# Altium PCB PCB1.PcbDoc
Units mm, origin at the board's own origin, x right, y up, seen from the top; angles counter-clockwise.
Board outline 100 x 100 mm, 4 copper layers (Top Layer, Layer 1, Layer 2, Bottom Layer), stack 1.578 mm thick; 83 components, 35 nets, 174 pads, 412 vias.
Unrouted connection lines stored in the file: 39.
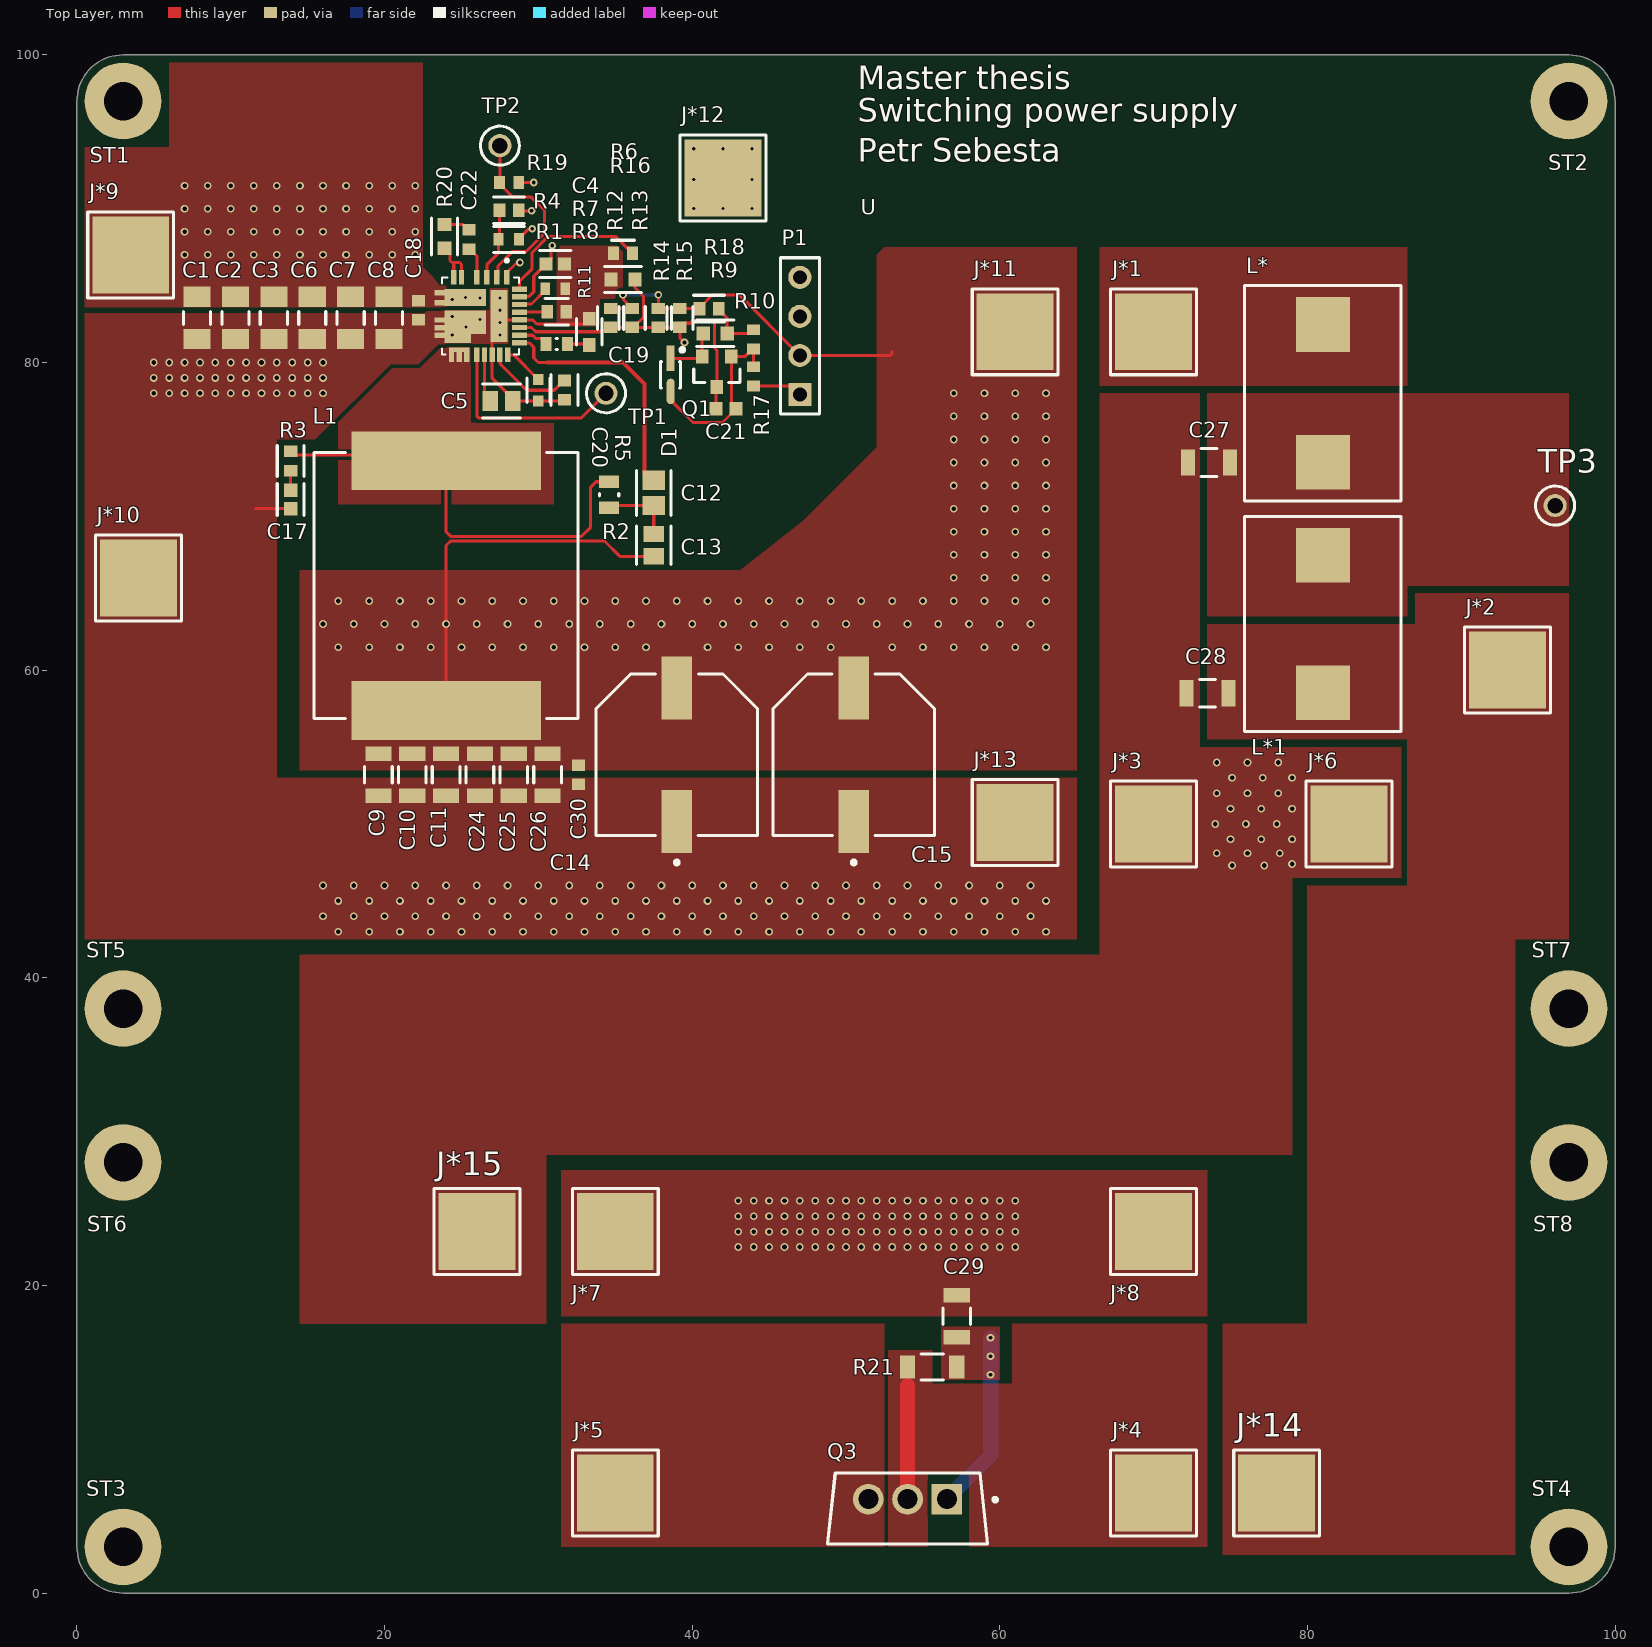
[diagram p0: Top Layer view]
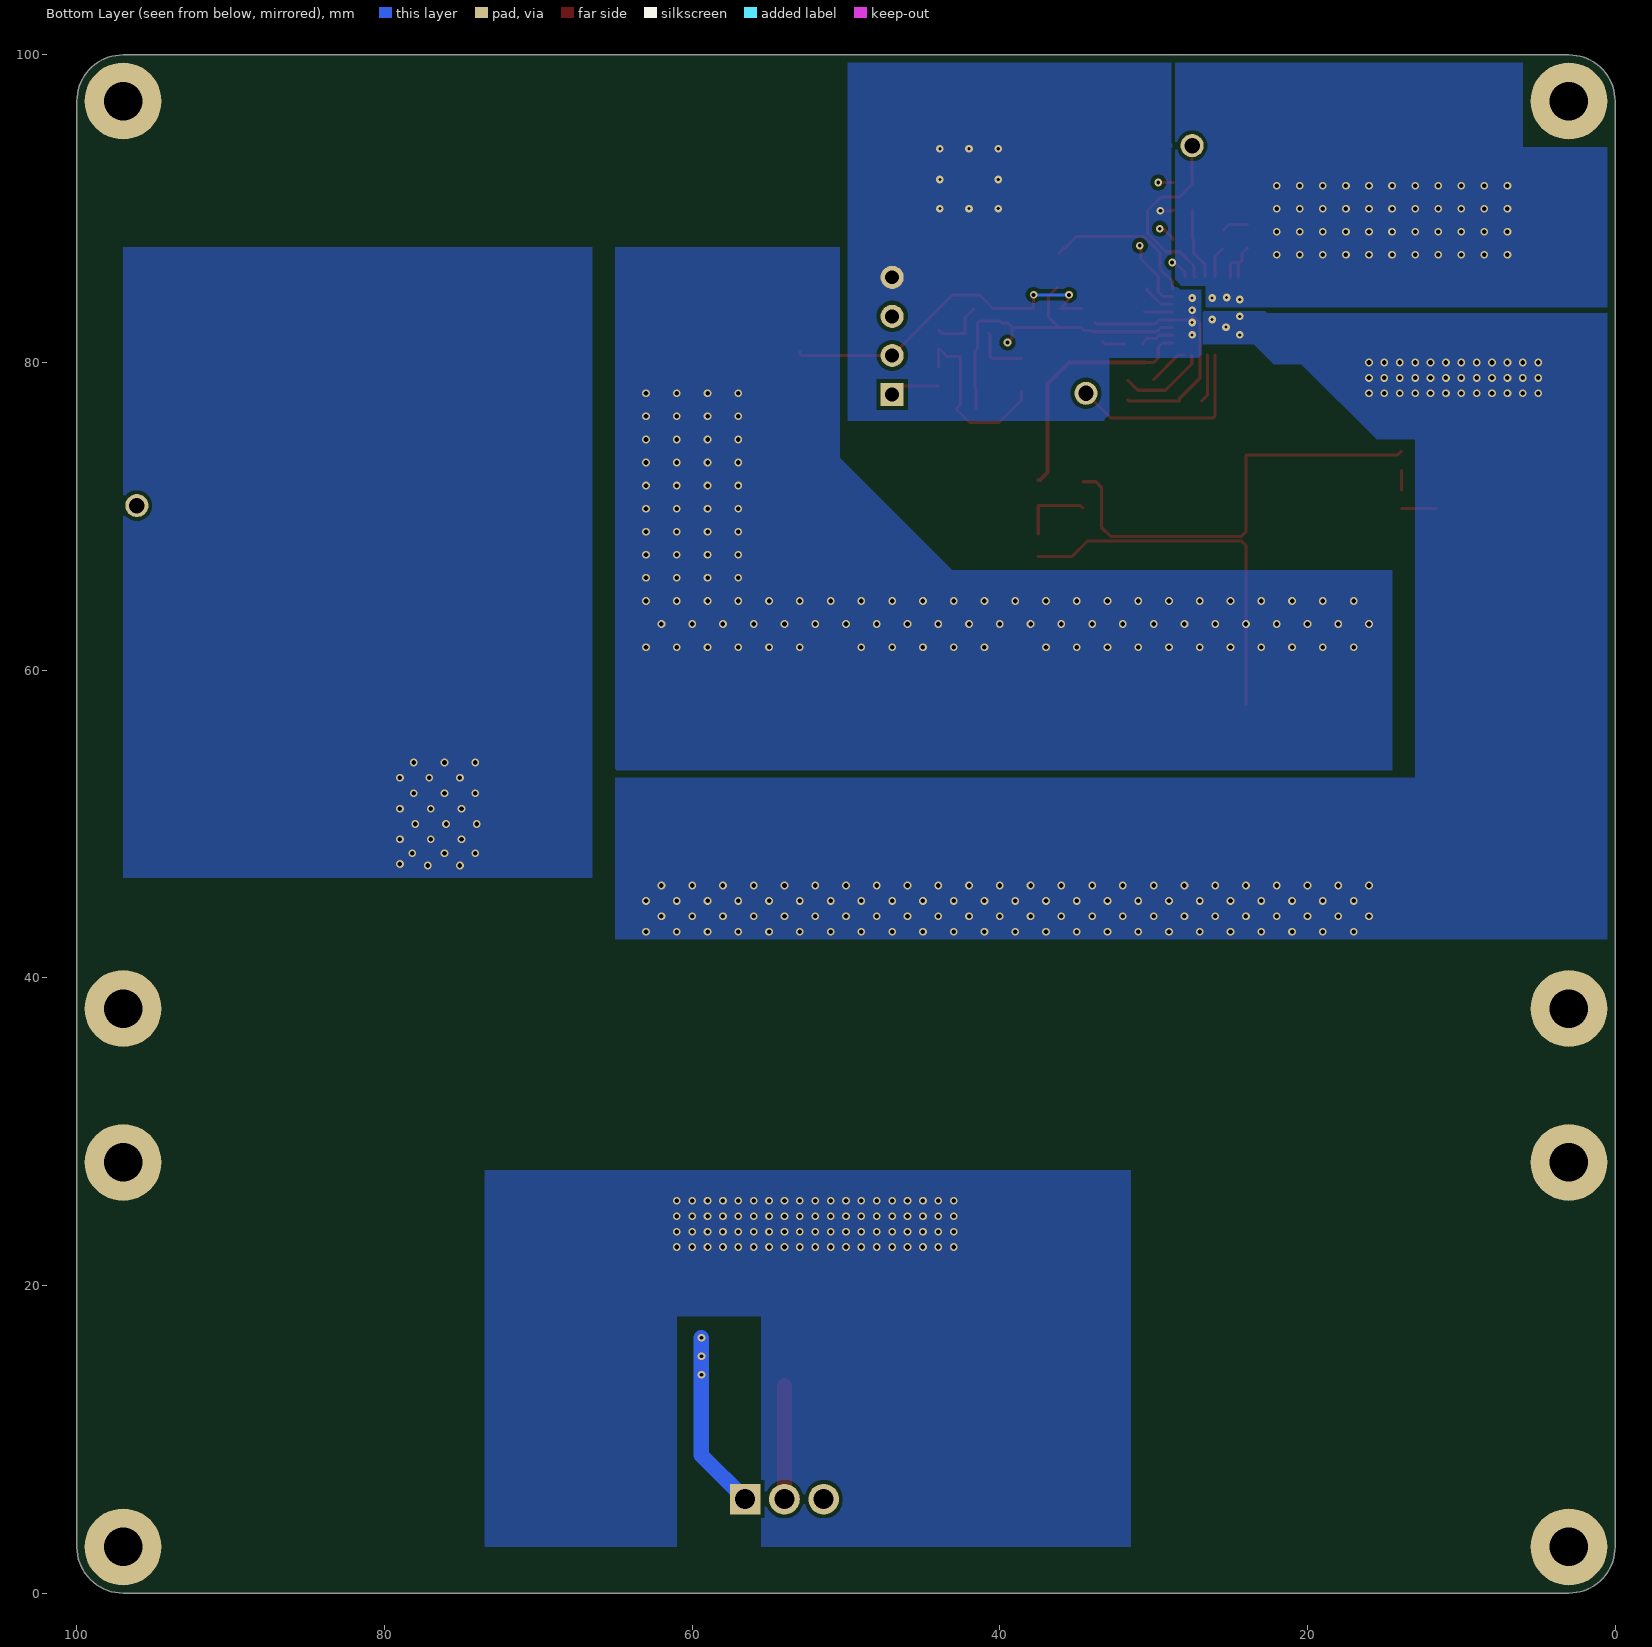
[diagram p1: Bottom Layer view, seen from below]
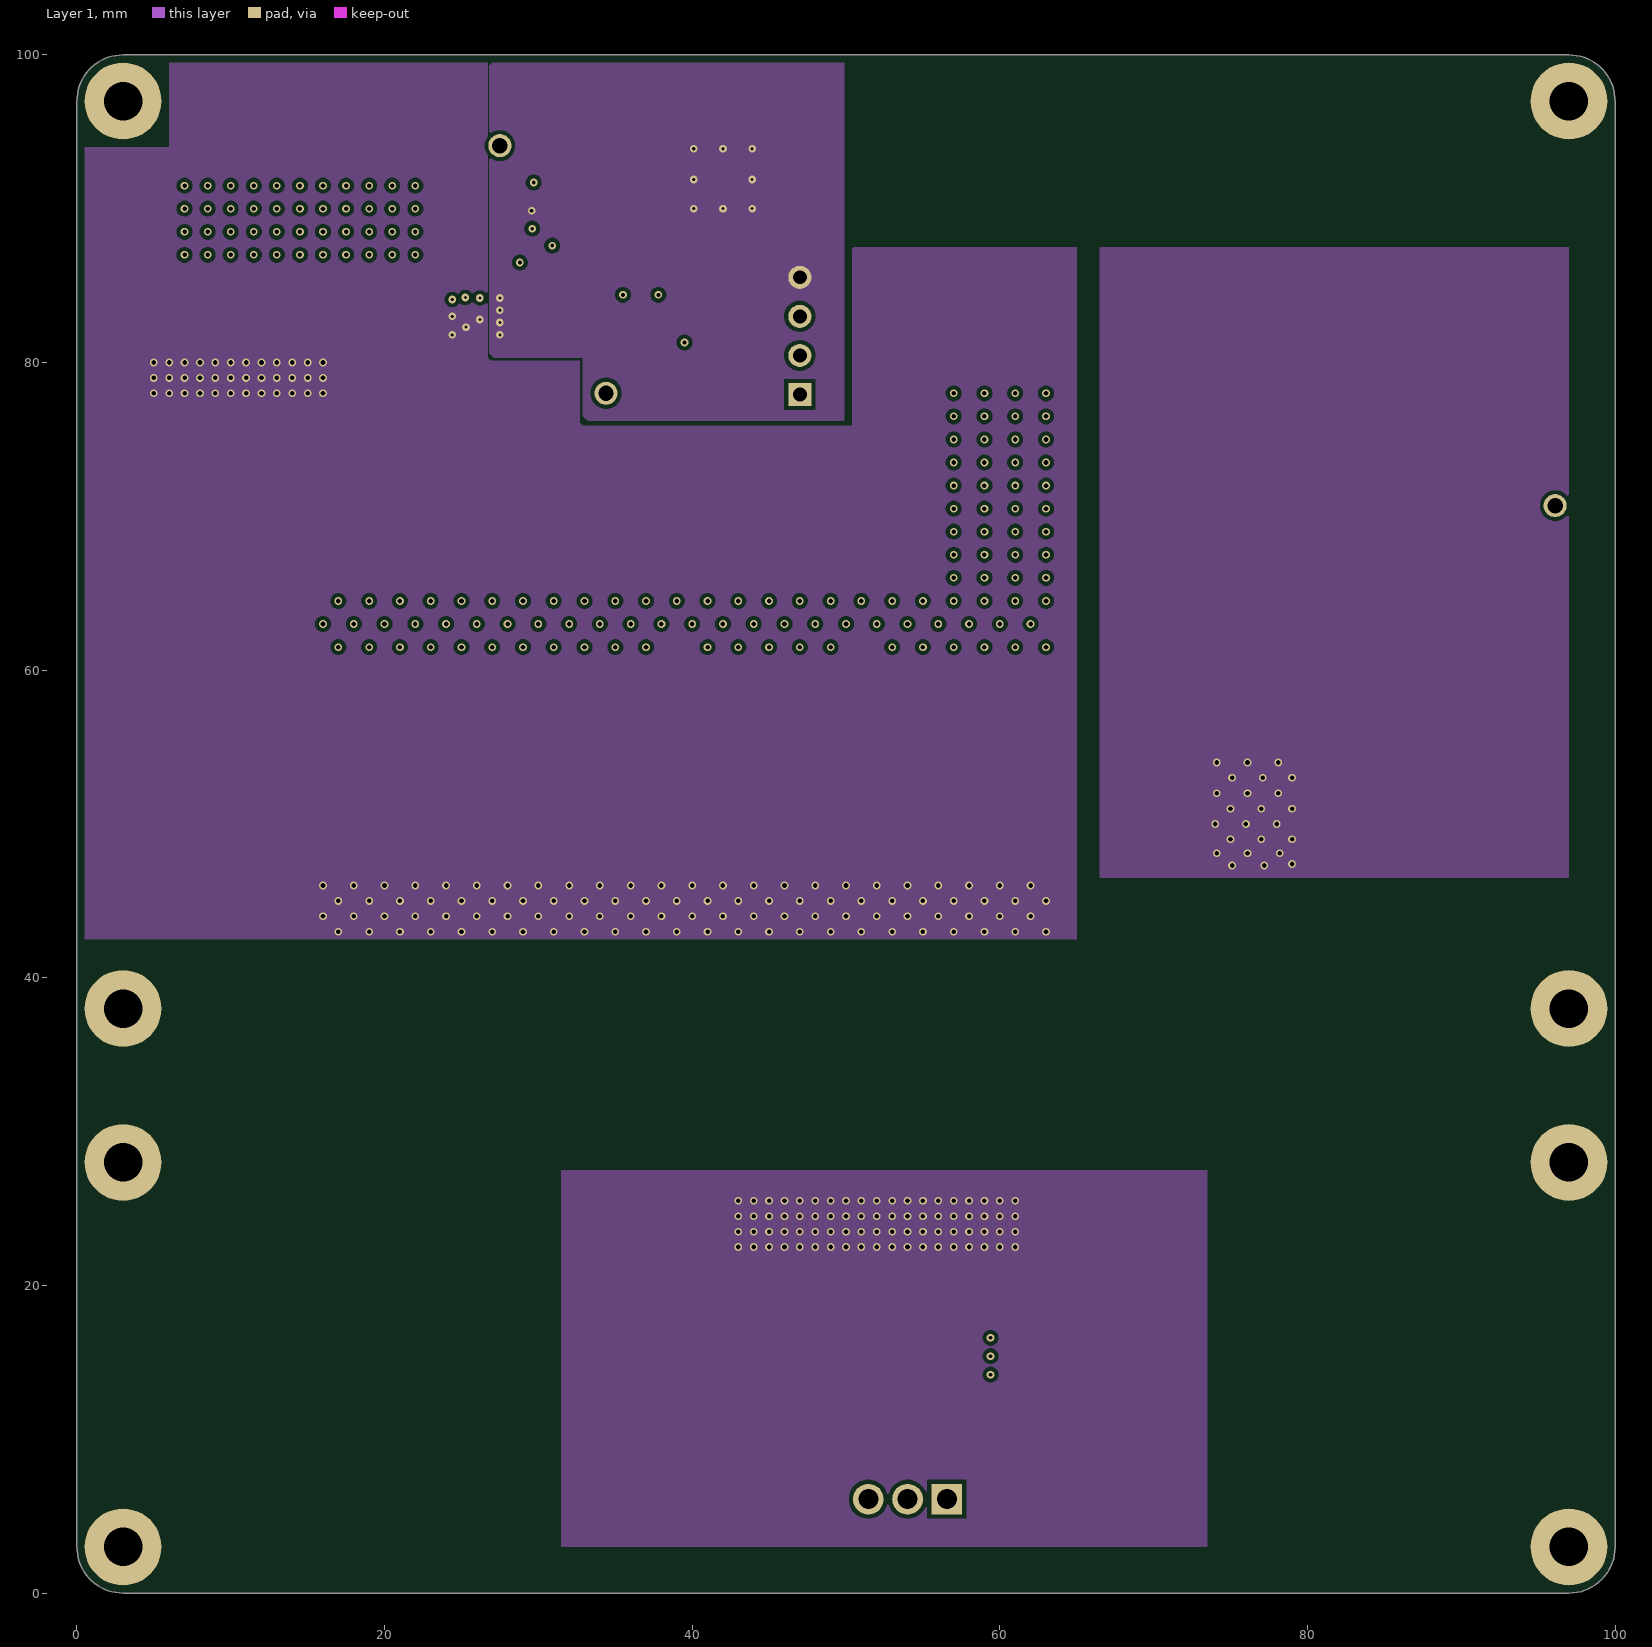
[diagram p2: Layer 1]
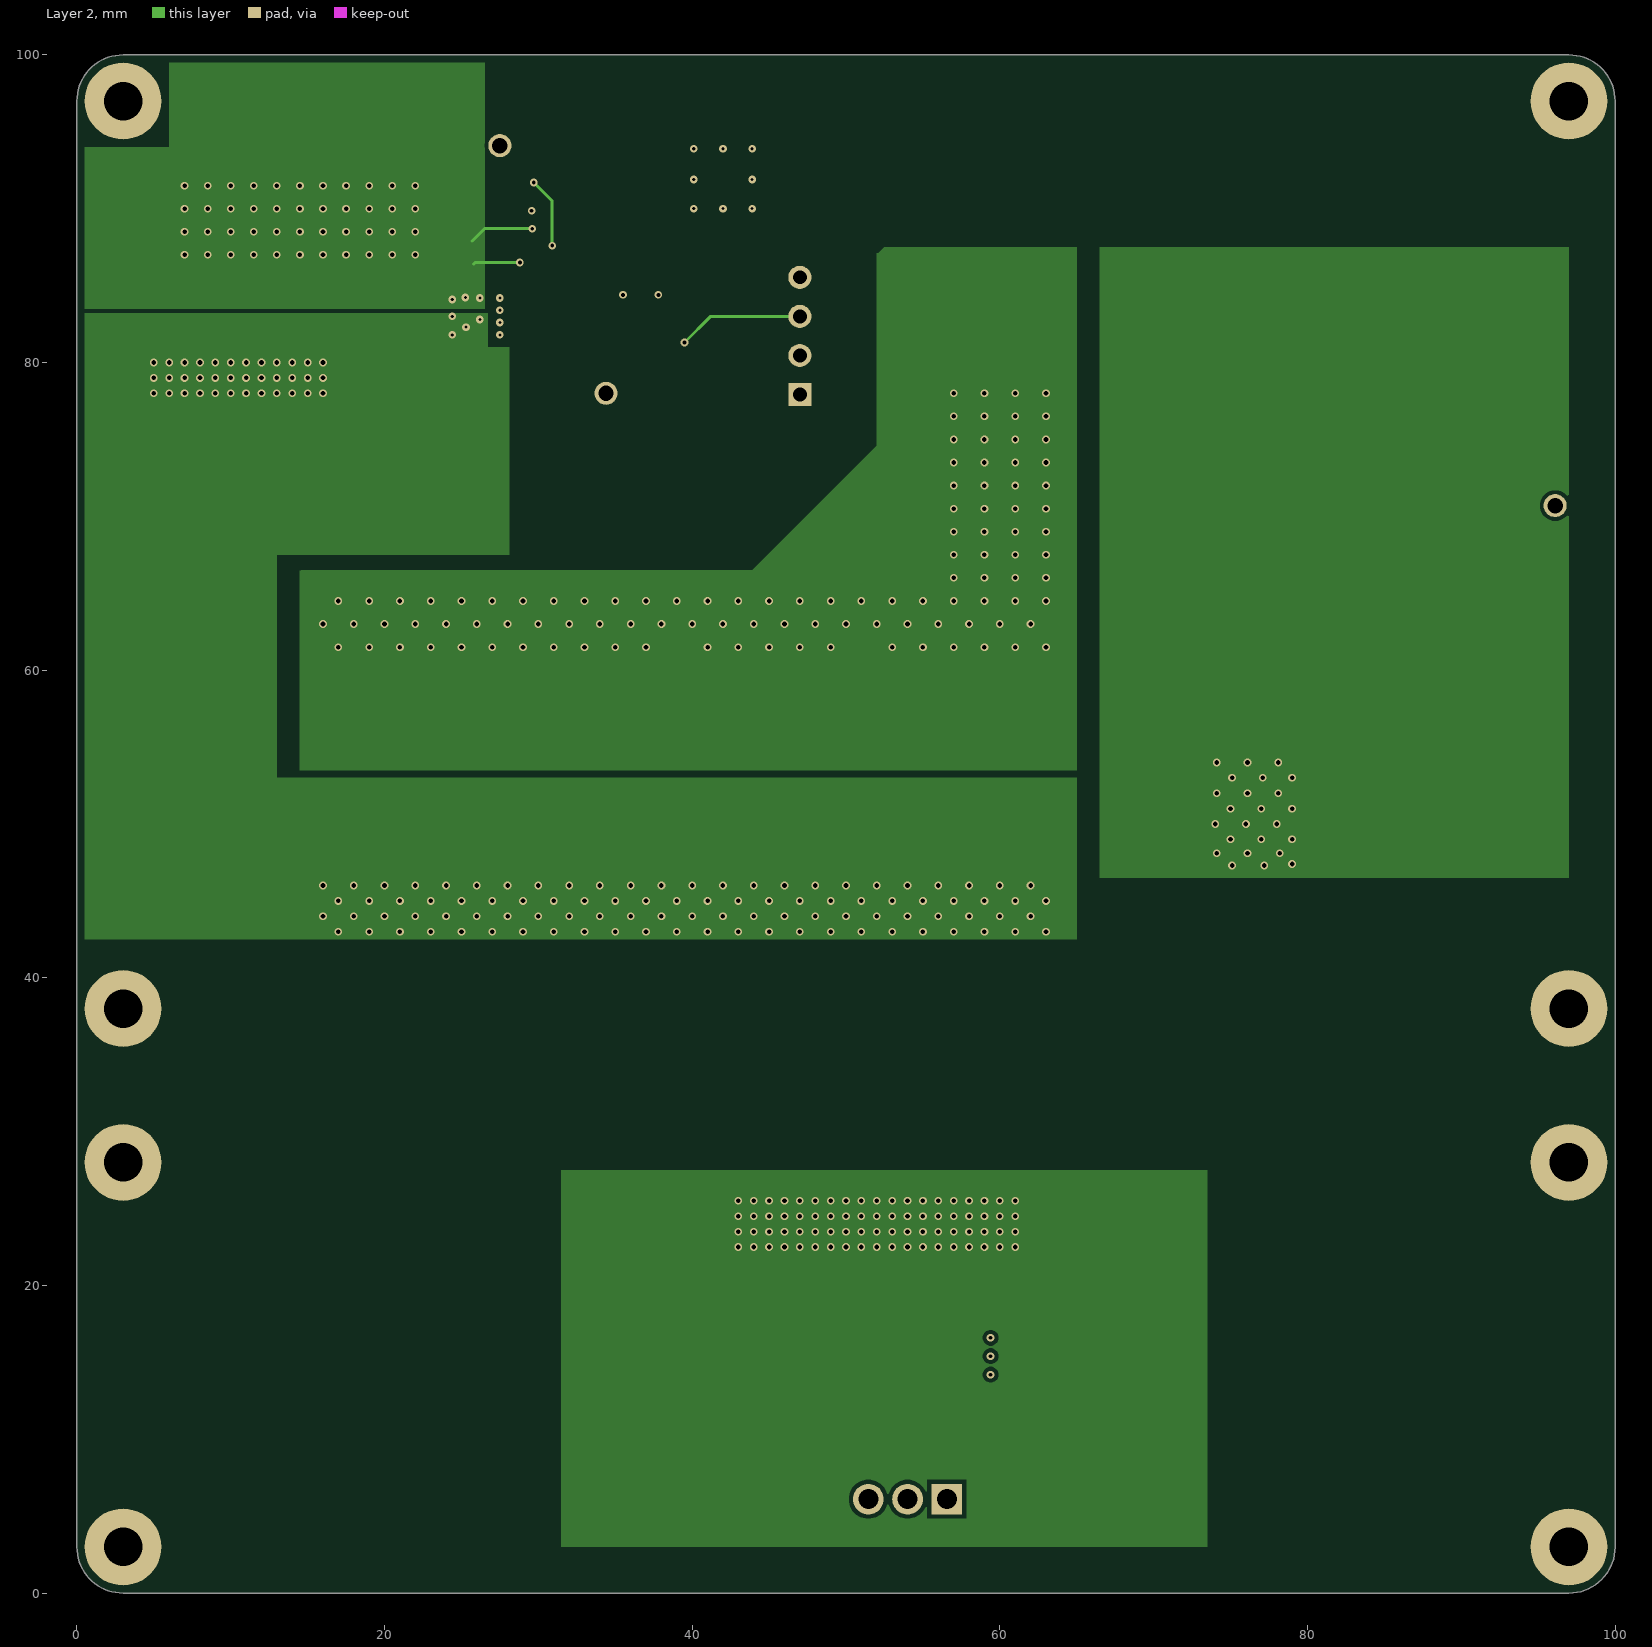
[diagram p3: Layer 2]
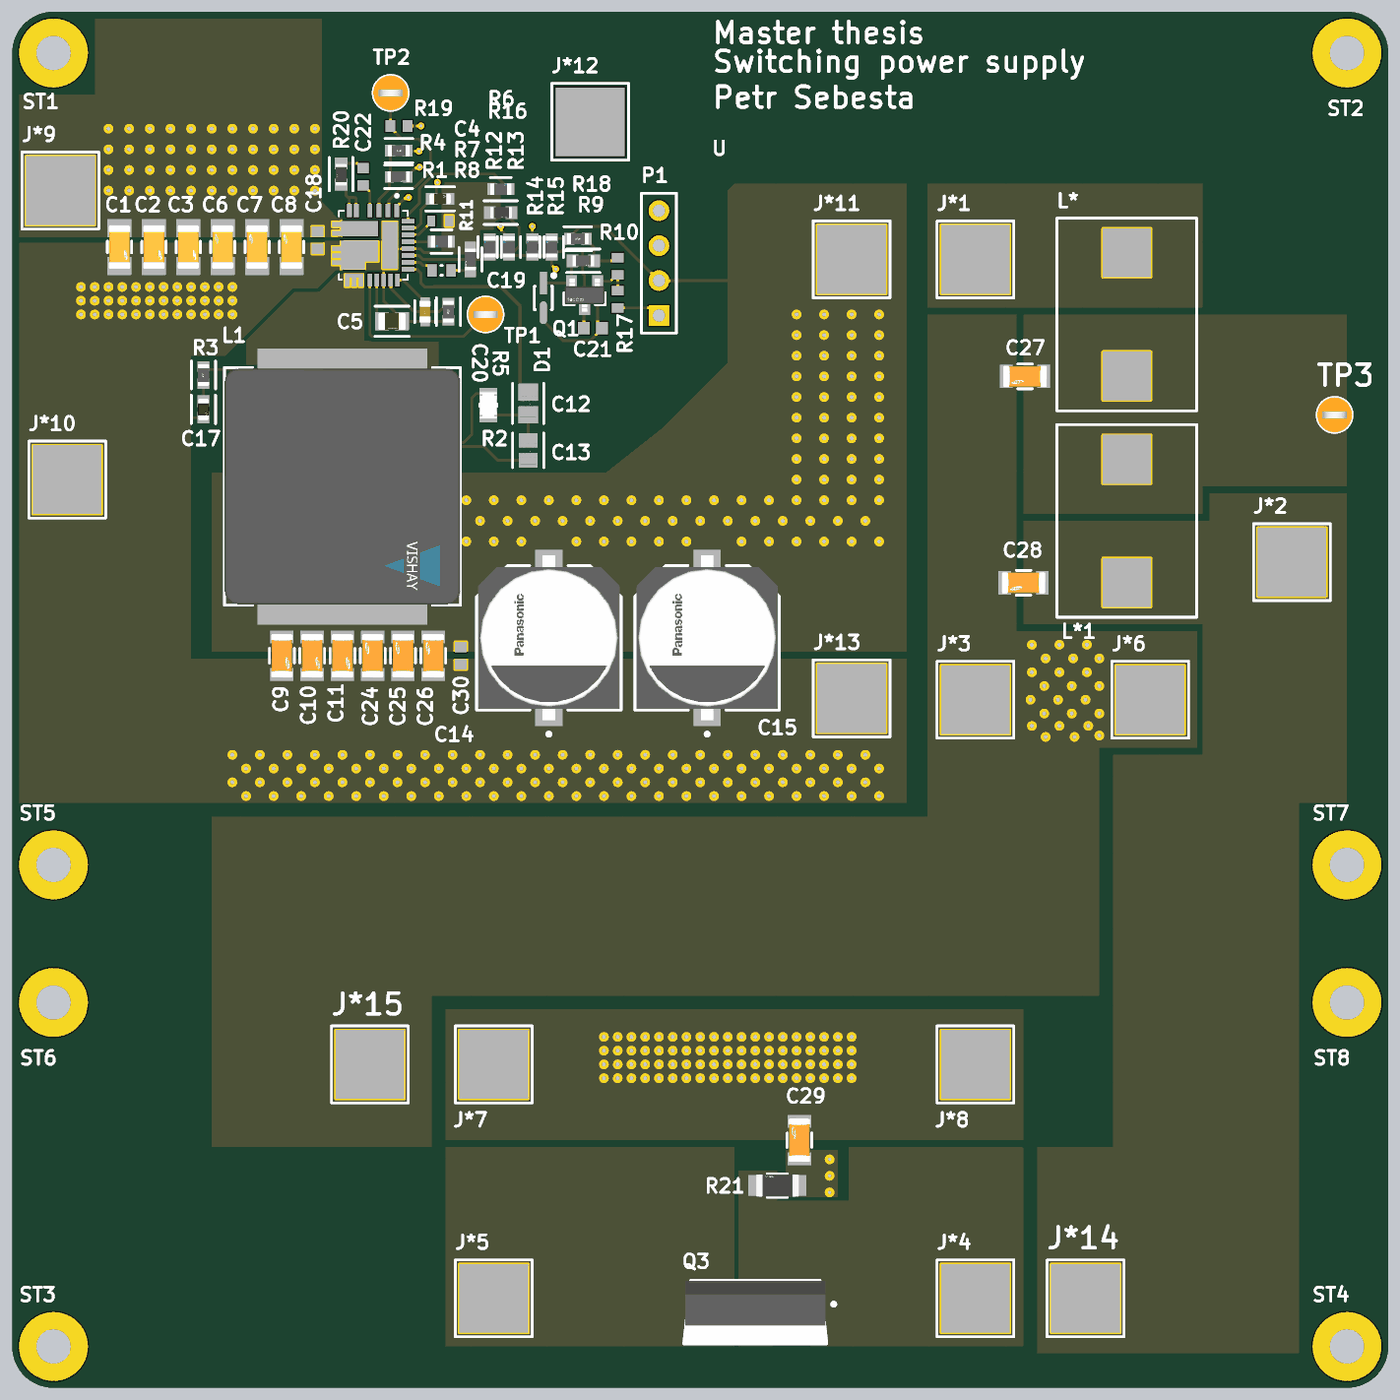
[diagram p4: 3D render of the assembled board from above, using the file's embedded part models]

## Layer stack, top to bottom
Top Solder: solder mask 0.0203, Solder Resist, Dk 3.8
Top Layer: signal copper 0.0356
Dielectric 2: prepreg 0.2104, PP-006, Dk 4.6
Layer 1: signal copper 0.0152
Dielectric 1: dielectric 1.056, FR-4, Dk 4.6
Layer 2: signal copper 0.0152
Dielectric 3: prepreg 0.2104, PP-006, Dk 4.6
Bottom Layer: signal copper 0.0356
Bottom Solder: solder mask 0.0203, Solder Resist, Dk 3.8

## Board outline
0,3 0,97 cw(c3,97) 3,100 97,100 cw(c97,97) 100,97 100,3 cw(c97,3) 97,0 3,0 cw(c3,3)

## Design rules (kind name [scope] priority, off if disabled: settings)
Clearance [All] p1: gap=0.254 ignorepadtopadclearanceinfootprint=FALSE except(0: Arc-Hole Track-Hole SMDPad-Hole THPad-Hole Via-Hole Fill-Hole Poly-Hole Region-Hole Text-Hole; 0.1: Arc-Arc Arc-Track Track-Track; 0.127: SMDPad-SMDPad; 0.2: Arc-SMDPad Track-SMDPad)
MinimumSolderMaskSliver [All] p1: minsoldermaskwidth=0
PolygonConnect PolygonConnect_18 [All vs IsNamedPolygon('NONET_L01_P-001') Or IsNamedPolygon('NONET_L01_P-001') Or IsNamedPolygon('NONET_L01_P-001') Or IsNamedPolygon('NONET_L01_P-001') Or IsNamedPolygon('NONET_L01_P-001') Or IsNamedPolygon('NONET_L01_P-001') Or IsNamedPolygon('NONET_L01_P-001')] p1: connectstyle=Direct reliefconductorwidth=0.254 reliefentries=4 polygonreliefangle="90 Angle" airgapwidth=0.254
PolygonConnect PolygonConnect_17 [All vs IsNamedPolygon('AGND_L02_P016') Or IsNamedPolygon('AGND_L02_P020') Or IsNamedPolygon('AGND_L03_P014') Or IsNamedPolygon('VCC_L03_P008') Or IsNamedPolygon('VOUT_L03_P015') Or IsNamedPolygon('AGND_L04_P022') Or IsNamedPolygon('AGND_L04_P024') Or IsNamedPolygon('VOUT_L04_P023') Or IsNamedPolygon('VCC_L04_P021')] p2: connectstyle=Direct reliefconductorwidth=0.254 reliefentries=4 polygonreliefangle="90 Angle" airgapwidth=0.254
PolygonConnect PolygonConnect_16 [All vs IsNamedPolygon('VOUT_L01_P010')] p3: connectstyle=Direct reliefconductorwidth=0.254 reliefentries=4 polygonreliefangle="90 Angle" airgapwidth=0.254
PolygonConnect PolygonConnect_15 [All vs IsNamedPolygon('VCC_L01_P000')] p4: connectstyle=Direct reliefconductorwidth=0.254 reliefentries=4 polygonreliefangle="90 Angle" airgapwidth=0.254
PolygonConnect PolygonConnect_14 [All vs IsNamedPolygon('AGND_L01_P011')] p5: connectstyle=Direct reliefconductorwidth=0.254 reliefentries=4 polygonreliefangle="90 Angle" airgapwidth=0.254
PolygonConnect PolygonConnect_13 [All vs IsNamedPolygon('AGND_L01_P007')] p6: connectstyle=Direct reliefconductorwidth=0.254 reliefentries=4 polygonreliefangle="90 Angle" airgapwidth=0.254
PolygonConnect PolygonConnect_12 [All vs IsNamedPolygon('AGND_L01_P006')] p7: connectstyle=Direct reliefconductorwidth=0.254 reliefentries=4 polygonreliefangle="90 Angle" airgapwidth=0.254
PolygonConnect PolygonConnect_11 [All vs IsNamedPolygon('AGND_L01_P006')] p8: connectstyle=Direct reliefconductorwidth=0.254 reliefentries=4 polygonreliefangle="90 Angle" airgapwidth=0.254
PolygonConnect PolygonConnect_10 [All vs IsNamedPolygon('AGND_L01_P005')] p9: connectstyle=Direct reliefconductorwidth=0.254 reliefentries=4 polygonreliefangle="90 Angle" airgapwidth=0.254
PolygonConnect PolygonConnect_9 [All vs IsNamedPolygon('AGND_L01_P005')] p10: connectstyle=Direct reliefconductorwidth=0.254 reliefentries=4 polygonreliefangle="90 Angle" airgapwidth=0.254
PolygonConnect PolygonConnect_8 [All vs IsNamedPolygon('AGND_L01_P004')] p11: connectstyle=Direct reliefconductorwidth=0.254 reliefentries=4 polygonreliefangle="90 Angle" airgapwidth=0.254
PolygonConnect PolygonConnect_7 [All vs IsNamedPolygon('AGND_L01_P003')] p12: connectstyle=Direct reliefconductorwidth=0.254 reliefentries=4 polygonreliefangle="90 Angle" airgapwidth=0.254
PolygonConnect DirectConnect [All vs IsNamedPolygon('AGND_L01_P001')] p13: connectstyle=Direct reliefconductorwidth=0.254 reliefentries=4 polygonreliefangle="90 Angle" airgapwidth=0.254
PolygonConnect PolygonConnect_6 [All vs IsNamedPolygon('GND_L01_P003')] p14: connectstyle=Direct reliefconductorwidth=0.254 reliefentries=4 polygonreliefangle="90 Angle" airgapwidth=0.254
PolygonConnect PolygonConnect_5 [All vs IsNamedPolygon('NETL1_1_L01_P002')] p15: connectstyle=Direct reliefconductorwidth=0.254 reliefentries=4 polygonreliefangle="90 Angle" airgapwidth=0.254
PolygonConnect PolygonConnect_4 [All vs IsNamedPolygon('GND_L01_P001')] p16: connectstyle=Direct reliefconductorwidth=0.254 reliefentries=4 polygonreliefangle="90 Angle" airgapwidth=0.254
PolygonConnect PolygonConnect_3 [All vs IsNamedPolygon('VCC_L01_P000')] p17: connectstyle=Direct reliefconductorwidth=0.254 reliefentries=4 polygonreliefangle="90 Angle" airgapwidth=0.254
PolygonConnect PolygonConnect_2 [All vs IsNamedPolygon('VCC_L01_P-001')] p18: connectstyle=Direct reliefconductorwidth=0.254 reliefentries=4 polygonreliefangle="90 Angle" airgapwidth=0.254
PolygonConnect PolygonConnect_1 [All vs IsNamedPolygon('VCC_L01_P000')] p19: connectstyle=Direct reliefconductorwidth=0.254 reliefentries=4 polygonreliefangle="90 Angle" airgapwidth=0.254
PolygonConnect [All] p20: connectstyle=Relief reliefconductorwidth=0.254 reliefentries=4 polygonreliefangle="90 Angle" airgapwidth=0.254
RoutingVias [All] p1: holewidth=0.25 width=0.5 viastyle="Through Hole" minholewidth=0.2 minwidth=0.5 maxholewidth=3.6 maxwidth=10
SilkToSilkClearance [All] p1: silktosilkclearance=0
SilkToSolderMaskClearance [IsPad] p1: minsilkscreentomaskgap=0 clearancetoexposedcopper=TRUE
SolderMaskExpansion [All] p1: expansion=0.102 istentingtop=FALSE
Width [All] p1: maxlimit=1 minlimit=0.2 preferedwidth=0.2
27 further rules are at their usual default settings.

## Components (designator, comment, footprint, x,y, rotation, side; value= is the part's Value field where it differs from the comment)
C1 "CL31B225KBHNNNF" FP-CL31-IPC_B 7.8,82.9 r270 top
C2 "CL31B225KBHNNNF" FP-CL31-IPC_B 10.3,82.9 r270 top
C3 "CL31B225KBHNNNF" FP-CL31-IPC_B 12.8,82.9 r270 top
C4 "UMK107AB7105KA-T" FP-0603-L_1_6_0_15-W_0_8-IPC_C 31.1,86.4 r0 top
C5 "TMK212AB7475KG-T" FP-0805-L_2_0_0_15-W_1_25-IPC_C 27.6,77.5 r0 top
C6 "CL31B225KBHNNNF" FP-CL31-IPC_B 15.3,82.9 r90 top
C7 "CL31B225KBHNNNF" FP-CL31-IPC_B 17.8,82.9 r90 top
C8 "CL31B225KBHNNNF" FP-CL31-IPC_B 20.3,82.9 r90 top
C9 "CL31B106KBHNNNE" FP-CL31B106KBHNNNE-MFG 19.6,53.2 r270 top value=10uF
C10 "CL31B106KBHNNNE" FP-CL31B106KBHNNNE-MFG 21.8,53.2 r270 top value=10uF
C11 "CL31B106KBHNNNE" FP-CL31B106KBHNNNE-MFG 24,53.2 r270 top value=10uF
C12 "CL21B392KBANNNC" FP-CL21-IPC_B 37.5,71.526 r270 top
C13 "CL21B223KBANNWC" FP-CL21-IPC_C 37.5,68.126 r270 top
C14 "EEEFP1V331AP" FP-FPG-MFG 39,54.5 r90 top
C15 "EEEFP1V331AP" FP-FPG-MFG 50.5,54.5 r90 top
C17 "UMK107AB7105KA-T" FP-0603-L_1_6_0_15-W_0_8-IPC_C 13.9,71.1 r270 top
C18 "CL10B104KB8NNNC" SAMS-C0603-2_L 22.2,83.4 r90 top
C19 "CAP 680pF 50V 0603(1608)" CAPC0603(1608)100_L 31.2,81.2 r180 top value=680pF
C20 "C1608X7R1H103M080AA" FP-C1608-080-0_1-MFG 30,78.2 r90 top
C21 "06035C471K4T2A" CAPC1608X90X35LL15T15 42.2,77 r0 top value=470p
C22 "CL10B104KB8NNNC" SAMS-C0603-2_L 25.5,88 r90 top
C24 "CL31B106KBHNNNE" FP-CL31B106KBHNNNE-MFG 26.2,53.2 r90 top value=10uF
C25 "CL31B106KBHNNNE" FP-CL31B106KBHNNNE-MFG 28.4,53.2 r90 top value=10uF
C26 "CL31B106KBHNNNE" FP-CL31B106KBHNNNE-MFG 30.6,53.2 r90 top value=10uF
C27 "CL31B106KBHNNNE" FP-CL31B106KBHNNNE-MFG 73.6,73.5 r180 top value=10uF
C28 "CL31B106KBHNNNE" FP-CL31B106KBHNNNE-MFG 73.5,58.5 r180 top value=10uF
C29 "CL31B106KBHNNNE" FP-CL31B106KBHNNNE-MFG 57.2,18 r90 top value=10uF
C30 "CL10B104KB8NNNC" SAMS-C0603-2_L 32.6,53.2 r90 top
D1 "BAS316,115" FP-SOD323-IPC_A 38.6,79.2 r270 top
J*1 "Conn_5x5mm" Conn_5x5mm 70,82 r0 top
J*2 "Conn_5x5mm" Conn_5x5mm 93,60 r0 top
J*3 "Conn_5x5mm" Conn_5x5mm 70,50 r0 top
J*4 "Conn_5x5mm" Conn_5x5mm 70,6.5 r0 top
J*5 "Conn_5x5mm" Conn_5x5mm 35,6.5 r0 top
J*6 "Conn_5x5mm" Conn_5x5mm 82.7,50 r0 top
J*7 "Conn_5x5mm" Conn_5x5mm 35,23.5 r0 top
J*8 "Conn_5x5mm" Conn_5x5mm 70,23.5 r0 top
J*9 "Conn_5x5mm" Conn_5x5mm 3.5,87 r0 top
J*10 "Conn_5x5mm" Conn_5x5mm 4,66 r0 top
J*11 "Conn_5x5mm" Conn_5x5mm 61,82 r0 top
J*12 "Conn_5x5mm" Conn_5x5mm 42,92 r0 top
J*13 "Conn_5x5mm" Conn_5x5mm 61,50.1 r0 top
J*14 "Conn_5x5mm" Conn_5x5mm 78,6.5 r0 top
J*15 "Conn_5x5mm" Conn_5x5mm 26,23.5 r0 top
L1 "IHLP6767GZER100M01" FP-IHLP-6767GZ-FP_3_825x1-MFG 24,65.5 r270 top
L* "L" Inductance_SRP1038C-3R3M 81,78 r270 top
L*1 "L" Inductance_SRP1038C-3R3M 81,63 r270 top
P1 "Header 4" HDR1X4 47,77.92 r90 top
Q1 "MMBT5401-7-F" FP-SOT23-MFG 41.6,79.4 r270 top
Q3 "TIP31C" FP-TO-220-P0A0015988-MFG 54,5.5 r270 top
R1 "AC0603FR-07560KL" FP-AC0603-IPC_C 28.077,88 r0 top
R2 "CRCW08053K00FKEA" FP-CRCW0805-e3-IPC_C 34.6,71.4 r90 top
R3 "CRG0603ZR" FP-CRG0603-IPC_C 13.9,73.6 r90 top
R4 "CRG0603ZR" FP-CRG0603-IPC_C 28.1,89.9 r180 top
R5 "CRG0603ZR" FP-CRG0603-IPC_C 31.7,78.2 r90 top
R6 "CRCW0603301KFKEA" FP-CRCW0603-e3-IPC_C 35.5,87.1 r0 top
R7 "RC0603FR-0762KL" RESC1608X55X25LL10T15 31.1,84.8 r180 top
R8 "CRCW0603301KFKEA" FP-CRCW0603-e3-IPC_C 31.2,83.3 r180 top
R9 "AC0603FR-072K4L" FP-AC0603-IPC_B 41.5,81.9 r0 top
R10 "ERJ-3EKF1003V" RESC1608X55X30LL15T15 44,81.5 r90 top value=100k
R11 "AC0603FR-0747K5L" FP-AC0603-MFG 33.3,82 r270 top
R12 "CRCW0603301KFKEA" FP-CRCW0603-e3-IPC_C 34.7,82.9 r90 top
R13 "CRCW0603301KFKEA" FP-CRCW0603-e3-IPC_C 36.1,82.9 r90 top
R14 "CRCW0603301KFKEA" FP-CRCW0603-e3-IPC_C 37.8,82.9 r90 top
R15 "CRCW0603301KFKEA" FP-CRCW0603-e3-IPC_C 39.2,82.9 r90 top
R16 "RT0603FRE0710KL" FP-RT0603-IPC_B 35.5,85.4 r0 top value=10KΩ
R17 "ERJ-3EKF1003V" RESC1608X55X30LL15T15 44,79.1 r90 top value=100k
R18 "CRG0603ZR" FP-CRG0603-IPC_C 41.1,83.5 r180 top
R19 "ERJ-3EKF1003V" RESC1608X55X30LL15T15 28.1,91.7 r0 top value=100k
R20 "RT0603FRE073R3L" FP-RT0603-IPC_B 23.9,88.2 r270 top value=3.3Ω
R21 "RT1206FRE073R3L" FP-RT1206-MFG 55.6,14.7 r180 top value=3.3Ω
ST1 "PTH-M2D5X5" PTH-M2D5X5 3,97 r0 top
ST2 "PTH-M2D5X5" PTH-M2D5X5 97,97 r0 top
ST3 "PTH-M2D5X5" PTH-M2D5X5 3,3 r0 top
ST4 "PTH-M2D5X5" PTH-M2D5X5 97,3 r0 top
ST5 "PTH-M2D5X5" PTH-M2D5X5 3,38 r0 top
ST6 "PTH-M2D5X5" PTH-M2D5X5 3,28 r0 top
ST7 "PTH-M2D5X5" PTH-M2D5X5 97,38 r0 top
ST8 "PTH-M2D5X5" PTH-M2D5X5 97,28 r0 top
TP1 "5003" KSTN-5003 34.4,78 r0 top
TP2 "5003" KSTN-5003 27.5,94.1 r0 top
TP3 "5003" KSTN-5003 96.1,70.7 r0 top
U "SIC461ED-T1-GE3" CONV_SIC461ED-T1-GE3 26.25,83.025 r270 top

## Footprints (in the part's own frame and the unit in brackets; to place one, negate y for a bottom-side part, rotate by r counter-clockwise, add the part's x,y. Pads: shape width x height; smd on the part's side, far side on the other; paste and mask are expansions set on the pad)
CAPC0603(1608)100_L [mm] "Chip Capacitor, Body 1.6x0.8mm, Height 1.0mm, IPC High Density"
  rect 0.7x0.9 smd: 1(-0.7,0) 2(0.7,0)
  silkscreen extent -0.05,-0.35 0.05,0.35, body extent -0.87,-0.47 0.88,0.48, height 1
CAPC1608X90X35LL15T15 [mm] "Chip Capacitor, 2-Leads, Body 1.60x0.81mm, IPC High Density"
  rect 0.85x0.9 smd: 1(-0.65,0) 2(0.65,0)
  body extent -0.88,-0.48 0.87,0.48, height 0.9
Conn_5x5mm [mm]
  rect 5x5 smd: 1(0,0)
  silkscreen extent -2.79,-2.79 2.79,2.79
CONV_SIC461ED-T1-GE3 [mm]
  rect 0.95x0.35 smd: 1(-2.525,1.7) 2(-2.525,1.05) 3(-2.525,0.4) 4(-2.525,-0.25) 5(-2.525,-1.25) 6(-2.525,-1.75) 12(2.525,-1.9) 13(2.525,-1.4) 14(2.525,-0.9) 15(2.525,-0.25) 16(2.525,0.25) 17(2.525,0.75) 18(2.525,1.25) 19(2.525,1.75)
  rect 0.35x0.95 smd: 7(-1.52,-2.525) 8(-0.87,-2.525) 9(0.26,-2.525) 10(0.76,-2.525) 11(1.26,-2.525) 20(1.75,2.525) 21(1.25,2.525) 22(0.75,2.525) 23(0.25,2.525) 24(-0.25,2.525) 25(-0.75,2.525) 26(-1.25,2.525) 27(-1.75,2.525)
  rect 0.3x1.35 smd: 14.1(2.2,-1.4)
  rect 3.4x1.1 smd: 28(0,1.2)
  rect 1.1x2.7 smd: 29(-1.2,-1)
  rect 1.52x2.7 smd: 30.1(0.41,-1)
  rect 2.1x1.73 smd: 30.2(0.7,-1.485)
  silkscreen extent -3.7,-2.5 2.5,2.5
FP-0603-L_1_6_0_15-W_0_8-IPC_C [mm]
  rect 0.858x0.862 smd paste+0 mask+0: 1(-0.602,0) 2(0.602,0)
  silkscreen extent -1.03,-0.87 1.03,0.87, body extent -1.13,-0.58 1.13,0.58, height 0.25
FP-0805-L_2_0_0_15-W_1_25-IPC_C [mm]
  rect 1.008x1.312 smd paste+0 mask+0: 1(-0.727,0) 2(0.727,0)
  silkscreen extent -1.23,-1.1 1.23,1.1, body extent -1.33,-0.8 1.33,0.8, height 0.25
FP-AC0603-IPC_B [mm]
  rect 0.859x0.912 smd paste+0 mask+0: 1(-0.777,0) 2(0.777,0)
  silkscreen extent -1.21,-0.86 1.21,0.86, body extent -1.46,-0.71 1.46,0.71, height 0.25
FP-AC0603-IPC_C [mm]
  rect 0.659x0.812 smd paste+0 mask+0: 1(-0.677,0) 2(0.677,0)
  silkscreen extent -1.01,-0.85 1.01,0.85, body extent -1.11,-0.55 1.11,0.55, height 0.25
FP-AC0603-MFG [mm]
  rect 0.9x0.8 smd paste+0 mask+0: 1(-0.85,0) 2(0.85,0)
  silkscreen extent -0.85,-0.82 0.85,0.82, body extent -1.4,-0.55 1.4,0.55, height 0.25
FP-C1608-080-0_1-MFG [mm]
  rect 0.7x0.7 smd paste+0 mask+0: 1(-0.7,0) 2(0.7,0)
  silkscreen extent -0.8,-0.75 0.8,0.75, body extent -1.15,-0.55 1.15,0.55, height 0.25
FP-CL21-IPC_B [mm]
  rect 1.255x1.456 smd paste+0 mask+0: 1(-0.826,0) 2(0.826,0)
  silkscreen extent -1.45,-1.13 1.45,1.13, body extent -1.7,-0.98 1.7,0.98, height 0.25
FP-CL21-IPC_C [mm]
  rect 1.055x1.356 smd paste+0 mask+0: 1(-0.726,0) 2(0.726,0)
  silkscreen extent -1.25,-1.12 1.25,1.12, body extent -1.35,-0.82 1.35,0.82, height 0.25
FP-CL31-IPC_B [mm]
  rect 1.305x1.758 smd paste+0 mask+0: 1(-1.376,0) 2(1.376,0)
  silkscreen extent -0.42,-0.88 0.42,0.88, body extent -2.28,-1.13 2.28,1.13, height 0.25
FP-CL31B106KBHNNNE-MFG [mm]
  rect 0.925x1.7 smd paste+0 mask+0: 1(-1.362,0) 2(1.362,0)
  silkscreen extent -0.53,-0.9 0.53,0.9, body extent -1.92,-1 1.92,1, height 0.25
FP-CRCW0603-e3-IPC_C [mm]
  rect 0.735x0.862 smd paste+0 mask+0: 1(-0.615,0) 2(0.615,0)
  silkscreen extent -0.75,-0.85 0.75,0.85, body extent -1.08,-0.58 1.08,0.58, height 0.25
FP-CRCW0805-e3-IPC_C [mil]
  rect 31.75x51.5 smd paste+0 mask+0: 1(-33.5,0) 2(33.5,0)
  silkscreen extent -3,-25 3,25, body extent -53,-31 53,31, height 10
FP-CRG0603-IPC_C [mm]
  rect 0.758x0.858 smd paste+0 mask+0: 1(-0.627,0) 2(0.627,0)
  silkscreen extent -1.01,-0.87 1.01,0.87, body extent -1.11,-0.58 1.11,0.58, height 0.25
FP-FPG-MFG [mm]
  rect 4.1x2 smd paste+0 mask+0: 1(-4.35,0) 2(4.35,0)
  silkscreen extent -7.12,-5.25 5.25,5.25, body extent -6.65,-5.5 6.65,5.5, height 0.25
FP-IHLP-6767GZ-FP_3_825x1-MFG [mm]
  rect 3.825x12.32 smd paste+0 mask+0: 1(-8.117,0) 2(8.117,0)
  silkscreen extent -8.64,-8.57 8.64,8.57, body extent -10.13,-8.67 10.13,8.67, height 0.25
FP-RT0603-IPC_B [mm]
  rect 0.859x0.912 smd paste+0 mask+0: 1(-0.777,0) 2(0.777,0)
  silkscreen extent -1.21,-0.86 1.21,0.86, body extent -1.46,-0.71 1.46,0.71, height 0.25
FP-RT1206-MFG [mm]
  rect 1x1.5 smd paste+0 mask+0: 1(-1.6,0) 2(1.6,0)
  silkscreen extent -0.72,-0.85 0.72,0.85, body extent -2.2,-0.95 2.2,0.95, height 0.25
FP-SOD323-IPC_A [mm]
  rect 1.655x0.516 smd paste+0 mask+0: 1(-1.075,0)
  rrect100% 1.655x0.516 smd paste+0 mask+0: 2(1.075,0)
  silkscreen extent -1.75,-0.65 0.85,0.88
FP-SOT23-MFG [mm]
  rect 0.9x0.8 smd paste+0 mask+0: 1(-1,0.95) 2(-1,-0.95) 3(1,0)
  silkscreen extent -0.18,-1.5 0.7,1.5, body extent -1.55,-1.6 1.55,1.6, height 0.25
FP-TO-220-P0A0015988-MFG [mm]
  rect 2x2 hole 1.3 paste-1000 mask+0: 1(-0.607,2.55)
  round 2 hole 1.3 paste-1000 mask+0: 2(-0.607,0) 3(-0.607,-2.55)
  silkscreen extent -2.3,-5.2 2.3,5.82, body extent -2.4,-5.3 2.4,5.3, height 0.25
HDR1X4 [mm] "Connector; Header; 4 Position"
  rect 1.5x1.5 hole 0.9: 1(0,0)
  round 1.5 hole 0.9: 2(2.54,0) 3(5.08,0) 4(7.62,0)
  silkscreen extent -1.27,-1.27 8.89,1.27
Inductance_SRP1038C-3R3M [mm]
  rect 3.55x3.5 smd: 1(-4.475,0) 2(4.475,0)
  silkscreen extent -7,-5.08 7,5.08
KSTN-5003 [mm] "Test Point, Through Hole, Dia 2.54mm"
  round 1.5 hole 1: 1(0,0)
  silkscreen extent -1.27,-1.27 1.27,1.27, body extent -1.27,-1.27 1.27,1.27, height 4.57
PTH-M2D5X5 [mm]
  round 5 hole 2.5: 1(0,0)
RESC1608X55X25LL10T15 [mm] "Chip Resistor, 2-Leads, Body 1.60x0.80mm, IPC High Density"
  rect 0.6x0.8 smd: 1(-0.65,0) 2(0.65,0)
  body extent -0.85,-0.45 0.85,0.45, height 0.55
RESC1608X55X30LL15T15 [mm] "Chip Resistor, 2-Leads, Body 1.60x0.80mm, IPC High Density"
  rect 0.7x0.85 smd: 1(-0.625,0) 2(0.625,0)
  body extent -0.87,-0.48 0.87,0.48, height 0.55
SAMS-C0603-2_L [mm] "Chip Capacitor, 2-Leads, Body 1.70x0.90mm, IPC High Density"
  rect 0.75x0.85 smd: 1(-0.625,0) 2(0.625,0)
  body extent -0.85,-0.45 0.85,0.45, height 0.9

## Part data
C1 C2 C3 C6 C7 C8: library part CMP-13271-000591-1, "Cap Ceramic 2.2uF 50V X7R ±10% SMD 1206 +125°C Embossed T/R", Capacitance=2.2uF, Case/Package=1206, Dielectric=X7R, Max Operating Temperature=125°C, Min Operating Temperature=-55°C, Package Quantity=8000, Tolerance=10%, Voltage Rating=50V
C4: library part CMP-2000-07531-4, "Ceramic Capacitor General Use 1uF ±10% 50V X7R 0603", Capacitance=1uF, Case Code (Imperial)=0603, Case Code (Metric)=1608, Dielectric=X7R, Max Operating Temperature=125°C, Min Operating Temperature=-55°C, Package Quantity=1, Tolerance=10%, Voltage Rating=50V
C5: library part CMP-14477-004132-2, "Multilayer Ceramic Capacitor 4.7 uF 25V X7R 10% SMD 0805 T/R", Capacitance=4.7uF, Case Code (Imperial)=0805, Case Code (Metric)=2012, Dielectric=X7R, Max Operating Temperature=125°C, Min Operating Temperature=-55°C, Package Quantity=1, Resistor Type=Ceramic, Tolerance=10%, Voltage Rating=25V
C9 C10 C11 C24 C25 C26 C27 C28 C29: library part CMP-2000-07530-2, "CAP CER 10UF 50V X7R 1206", Capacitance=10uF, Manufacturer=Samsung, Temperature="-55°C to +125°C", Temperature Characteristic=X7R, Temperature Coefficient=15%, Temperature Range High=+125°C, Temperature Range Low=-55°C, Tolerance=10%, Voltage Rating=50V
C12: library part CMP-13271-000410-1, "CL21 Series 0805 3.9nF 50V ±10% Tolerance X7R Multilayer Ceramic Chip Capacitor", Capacitance=3.9nF, Case Code (Imperial)=0805, Case Code (Metric)=2012, Dielectric=X7R, Max Operating Temperature=125°C, Min Operating Temperature=-55°C, Package Quantity=1, Tolerance=10%, Voltage=50V
C13: library part CMP-13271-002873-1, "CL21 Series 0805 22nF 50V ±10% Tolerance X7R Multilayer Ceramic Chip Capacitor", Capacitance=22nF, Case Code (Imperial)=0805, Case Code (Metric)=2012, Dielectric=X7R, Max Operating Temperature=125°C, Min Operating Temperature=-55°C, Package Quantity=1, Tolerance=10%, Voltage Rating=50V
C14 C15: library part CMP-05427-000057-1, "CAP ALUM 330UF 20% 35V SMD", Capacitance=330uF, Case/Package=Radial, Dielectric Material=Aluminium, ESR (Equivalent Series Resistance)=60mR, Leakage Current=115.5uA, Max Operating Temperature=105°C, Min Operating Temperature=-55°C, Package Quantity=500, Ripple Current=1.19A, Tolerance=20%, Voltage=35V
C17: library part CMP-2000-07531-4, "Ceramic Capacitor General Use 1uF ±10% 50V X7R 0603", Capacitance=?, Case Code (Imperial)=0603, Case Code (Metric)=1608, Dielectric=X7R, Max Operating Temperature=125°C, Min Operating Temperature=-55°C, Package Quantity=1, Tolerance=10%, Voltage Rating=50V
C18 C22 C30: library part CMP-2000-05332-1, "Multi-layer Ceramic Capacitor, -55 to 125 degC, 2-Pin SMD (0603), RoHS, Tape and Reel", Capacitance=0.1µF, Case Size/Dimension=0603, Dielectric=X7R, Manufacturer="Samsung Electro-Mechanics", Rated Voltage=50V, Tolerance (%)=±10%
C19: library part CMP-1035-01782-1, "CAP 680pF 50V ±5% 0603 (1608 Metric) Thickness 1mm SMD", Case-EIA=0603, Case-Metric=1608, Rated Voltage="50 V", Tolerance=Â±5%
C20: library part CMP-08246-006703-1, "Multilayer Ceramic Capacitors 10nF ±20% 50V X7R SMD 0603", Capacitance=10nF, Case Code (Imperial)=0603, Case Code (Metric)=1608, Dielectric=X7R, Dielectric Material=Ceramic, Max Operating Temperature=125°C, Min Operating Temperature=-55°C, Package Quantity=1, Tolerance=20%, Voltage Rating=50V
C21: library part CMP-2006-02099-1, Manufacturer="AVX Interconnect / Elco"
D1: library part CMP-14399-000012-1, "DIODE GEN PURP 100V 250MA SOD323"
L1: library part CMP-02424-000414-1, "Commercial Inductors, High Saturation Series 10uH 16.5A 12mΩ 20%", Case/Package=6767, Current Rating=16.5A, DC Resistance (DCR)=12mR, Inductance=10uH, Inductance Tolerance=20%, Max DC Current=25A, Max Operating Temperature=125°C, Min Operating Temperature=-55°C, Package Quantity=200, Self Resonant Frequency=2MHz, Test Frequency=100kHz
L*: library part Inductance_SRP1038C-3R3M, "SRP1038C-3R3M 3.3 uH; 11.8 mOhms; 14 A"
L*1: library part Inductance_SRP1038C-3R3M, "SRP1038C-3R3M 3.3 uH; 11.8 mOhms; 14 A", Supplier Part Number 1=3280850
P1: "Header, 4-Pin"
Q1: library part CMP-12798-000015-1, "TRANS PNP 150V 0.6A SMD SOT23-3", Collector Base Voltage=-160V, Collector Emitter Breakdown Voltage=-150V, Collector Emitter Saturation Voltage=-0.5V, Emitter Base Voltage=-5V, Manufacturer="Diodes Inc.", Max Collector Current=-600mA, Max Junction Temp=+150°C, Package=SOT23, Power Dissipation=310mW, Temperature="-55°C to +150°C", Temperature Range Low=-55°C
Q3: library part CMP-12195-000001-1, "TRANS NPN 100V 3A TO-220", Collector Base Voltage=100V, Collector Emitter Saturation Voltage=1.2V, Emitter Base Voltage=5V, Manufacturer=STMicroelectronics, Max Collector Current=3A, Max Junction Temp=+150°C, Package=TO-220-P0A0015988, Power Dissipation=2W, Temperature="to +150°C"
R1: library part CMP-03412-028160-2, "RES 560KΩ 1.00% 0.1W 0603", Case Code (Imperial)=0603, Case Code (Metric)=1608, Max Operating Temperature=155°C, Max Power Dissipation=100mW, Min Operating Temperature=-55°C, Package Quantity=1, Ratings=AEC-Q200, Resistance=560kR, Resistor Type="Thick Film", Temperature Coefficient=100ppm/°C, Tolerance=1%, Voltage Rating=50V
R2: library part CMP-2001-03869-2, "RES Thick Film, 3kΩ, 1%, 0.125W, 100ppm/°C, 0805", Case Code (Imperial)=0805, Case Code (Metric)=2012, Max Operating Temperature=155°C, Max Power Dissipation=125mW, Min Operating Temperature=-55°C, Package Quantity=10, Resistance=3kR, Temperature Coefficient=100ppm/°C, Tolerance=1%, Voltage Rating=150V
R3: library part CMP-03211-011415-1, "RES SMD 0 OHM JUMPER 1/10W 0603", Case Code (Imperial)=0603, Case Code (Metric)=1608, Max Operating Temperature=125°C, Max Power Dissipation=100mW, Min Operating Temperature=-55°C, Number of Resistors=1, Package Quantity=5000, Resistance=?, Resistor Type="Thick Film", Temperature Coefficient=100ppm/°C, Tolerance=0%, Voltage Rating=50V
R4 R5 R18: library part CMP-03211-011415-1, "RES SMD 0 OHM JUMPER 1/10W 0603", Case Code (Imperial)=0603, Case Code (Metric)=1608, Max Operating Temperature=125°C, Max Power Dissipation=100mW, Min Operating Temperature=-55°C, Number of Resistors=1, Package Quantity=5000, Resistance=0mR, Resistor Type="Thick Film", Temperature Coefficient=100ppm/°C, Tolerance=0%, Voltage Rating=50V
R6 R8 R12 R13 R14 R15: library part CMP-2000-03218-2, "RES Thick Film, 301kΩ, 1%, 0.1W, 100ppm/°C, 0603", Case Code (Imperial)=0603, Case Code (Metric)=1608, Max Operating Temperature=155°C, Max Power Dissipation=100mW, Min Operating Temperature=-55°C, Package Quantity=10, Resistance=301kR, Temperature Coefficient=100ppm/°C, Tolerance=1%, Voltage Rating=75V
R7: library part CMP-2000-04104-1, Manufacturer=Yageo, Resistance=62kR
R9: library part CMP-03412-003336-2, "RES 2.4KΩ 1.00% 0.1W 0603", Case Code (Imperial)=0603, Case Code (Metric)=1608, Max Operating Temperature=155°C, Max Power Dissipation=100mW, Min Operating Temperature=-55°C, Ratings=AEC-Q200, Resistance=2.4kR, Resistor Type="Thick Film", Temperature Coefficient=100ppm/°C, Tolerance=1%, Voltage Rating=50V
R10 R17 R19: library part CMP-2000-00182-1, Manufacturer=Panasonic
R11: library part CMP-03412-027829-2, "RES 47.5KΩ 1.00% 0.1W 0603", Case Code (Imperial)=0603, Case Code (Metric)=1608, Max Operating Temperature=155°C, Max Power Dissipation=100mW, Min Operating Temperature=-55°C, Ratings=AEC-Q200, Resistance=47.5kR, Resistor Type="Thick Film", Temperature Coefficient=100ppm/°C, Tolerance=1%, Voltage Rating=50V
R16: library part CMP-03412-005349-1, "RES SMD 10K OHM 1% 1/10W 0603", Manufacturer=Yageo, Package=RT0603, Power Rating=0.1W, Resistance=10KΩ, Temperature="-55°C to +155°C", Temperature Coefficient="50 ppm/°C", Temperature Range High=+155°C, Temperature Range Low=-55°C, Tolerance=0.01, Voltage Rating=75V
R20: library part CMP-03412-003867-1, "RES SMD 3.3 OHM 1% 1/10W 0603", Manufacturer=Yageo, Package=RT0603, Power Rating=0.1W, Resistance=3.3Ω, Temperature="-55°C to +155°C", Temperature Coefficient="50 ppm/°C", Temperature Range High=+155°C, Temperature Range Low=-55°C, Tolerance=0.01, Voltage Rating=75V
R21: library part CMP-03412-007399-1, "RT1206 3.3Ω 0.25W 50 ppm/°C 0.02%", Manufacturer=Yageo, Package=RT1206, Power Rating=0.25W, Resistance=3.3Ω, Temperature="-55°C to +155°C", Temperature Coefficient="50 ppm/°C", Temperature Range High=+155°C, Temperature Range Low=-55°C, Tolerance=0.0002, Voltage Rating=200V
ST1 ST2 ST3 ST4 ST5 ST6 ST7 ST8: library part CMP-00028-00004-1, "M2 PTH (2.5mm), 5mm pad"
TP1 TP2 TP3: library part CMP-002-00037-1, "Test Point, Orange, Height 4.6 mm, Tail Length 3 mm, 1-Pin THD, RoHS", Colour=Orange, Manufacturer=Keystone, Package Description="1-Pin Through Hole Device, Dia 2.54 mm", Package Quantity=10
U: "Buck Switching Regulator IC Positive Adjustable 0.8V 1 Output 10A PowerPAKÂ® MLP55-27", Package="PowerPAKÂ®-55 Vishay Siliconix"

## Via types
v1: diameter 0.5, hole 0.3, Top Layer to Bottom Layer, 382 vias
v2: diameter 0.5, hole 0.2, Top Layer to Bottom Layer, 19 vias
v3: diameter 0.5, hole 0.25, Top Layer to Bottom Layer, 11 vias

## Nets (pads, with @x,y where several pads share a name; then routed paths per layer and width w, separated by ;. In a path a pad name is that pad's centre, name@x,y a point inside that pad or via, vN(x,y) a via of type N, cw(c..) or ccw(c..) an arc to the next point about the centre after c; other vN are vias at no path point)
AGND: C1.2 C2.2 C3.2 C4.2 C5.2 C6.1 C7.1 C8.1 C9.2 C10.2 C11.2 C14.1 C15.1 C17.2 C18.1 C20.1 C24.1 C25.1 C26.1 C30.1 J*10.1 J*12.1 J*13.1 P1.4 R4.1 R5.1 R6.1 R7.1 R8.1 R11.1 R16.1 U.9 U.10 U.11 U.17 U.23 U.28 U.30.1 U.30.2 | length 19.4
  Top Layer w0.2: 11.6,70.5 11.602,70.498 C17.2 ; R4.1 28.762,89.865 v3(29.565,89.865) ; R5.1 31.627,77.5 C20.1 C5.2 28.327,77.652 27,78.979 U.17 27,82.575 U.28 27.7,82.775 U.23 29.625,82.775 29.9,82.5 33.7,82.5 33.8,82.6
  other v1: 17,43 19,43 21,43 23,43 25,43 27,43 29,43 31,43 33,43 35,43 37,43 39,43 41,43 43,43 45,43 47,43 49,43 51,43 53,43 55,43 57,43 59,43 61,43 63,43 16,44 18,44 20,44 22,44 24,44 26,44 28,44 30,44 32,44 34,44 36,44 38,44 40,44 42,44 44,44 46,44 48,44 50,44 52,44 54,44 56,44 58,44 60,44 62,44 17,45 19,45 21,45 23,45 25,45 27,45 29,45 31,45 33,45 35,45 37,45 39,45 41,45 43,45 45,45 47,45 49,45 51,45 53,45 55,45 57,45 59,45 61,45 63,45 16,46 18,46 20,46 22,46 24,46 26,46 28,46 30,46 32,46 34,46 36,46 38,46 40,46 42,46 44,46 46,46 48,46 50,46 52,46 54,46 56,46 58,46 60,46 62,46 5,78 6,78 7,78 8,78 9,78 10,78 11,78 12,78 13,78 14,78 15,78 16,78 5,79 6,79 7,79 8,79 9,79 10,79 11,79 12,79 13,79 14,79 15,79 16,79 5,80 6,80 7,80 8,80 9,80 10,80 11,80 12,80 13,80 14,80 15,80 16,80
  other v2: 24.4,81.8 27.5,81.8 25.3,82.3 27.5,82.6 26.2,82.8 24.4,83 27.5,83.4 27.5,84.2 40.1,90 42,90 43.9,90 40.1,91.9 43.9,91.9 40.1,93.9 42,93.9 43.9,93.9
BGND: C29.2 J*7.1 J*8.1
  other v1: 43,22.5 44,22.5 45,22.5 46,22.5 47,22.5 48,22.5 49,22.5 50,22.5 51,22.5 52,22.5 53,22.5 54,22.5 55,22.5 56,22.5 57,22.5 58,22.5 59,22.5 60,22.5 61,22.5 43,23.5 44,23.5 45,23.5 46,23.5 47,23.5 48,23.5 49,23.5 50,23.5 51,23.5 52,23.5 53,23.5 54,23.5 55,23.5 56,23.5 57,23.5 58,23.5 59,23.5 60,23.5 61,23.5 43,24.5 44,24.5 45,24.5 46,24.5 47,24.5 48,24.5 49,24.5 50,24.5 51,24.5 52,24.5 53,24.5 54,24.5 55,24.5 56,24.5 57,24.5 58,24.5 59,24.5 60,24.5 61,24.5 43,25.5 44,25.5 45,25.5 46,25.5 47,25.5 48,25.5 49,25.5 50,25.5 51,25.5 52,25.5 53,25.5 54,25.5 55,25.5 56,25.5 57,25.5 58,25.5 59,25.5 60,25.5 61,25.5
FGND: C27.2 C28.2 J*3.1 J*6.1 J*15.1
  other v1: 75.1,47.3 77.2,47.3 79,47.4 74.1,48.1 76.1,48.1 78.2,48.1 75,49 77,49 79,49 74,50 76,50 78,50 75,51 77,51 79,51 74.1,52 76.1,52 78.1,52 75.1,53 77.1,53 79,53 74.1,54 76.1,54 78.1,54
NetC4_1: C4.1 R19.2 U.26 | length 10.1
  Top Layer w0.2: R19.2 v3(29.7,91.7) ; U.26 28.8,84.3 29.4,84.3 29.7,84.6 29.7,85.6 30.498,86.398 C4.1 30.827,86.729 30.827,87.446 30.9,87.519 v3(30.9,87.6)
  Layer 2 w0.2: v3(29.7,91.7) 30.9,90.5 v3(30.9,87.6)
NetC5_1: C5.1 U.16 | length 3.2
  Top Layer w0.2: U.16 26.5,77.873 C5.1
NetC12_1: C12.1 U.20 | length 16.2
  Top Layer w0.2: U.20 28.783,81.267 29.433,81.267 29.7,81 29.7,80.3 30,80 30.6,80
  Top Layer w0.252: 30.6,80 35.5,80 36.898,78.602 36.898,72.853 37.399,72.352 C12.1
NetC12_2: C12.2 C13.1 R2.1 | length 4.8
  Top Layer w0.2: R2.1 34.751,70.7 C12.2 C13.1
NetC17_1: C17.1 R3.1 | length 1.3
  Top Layer w0.2: C17.1 R3.1
NetC19_1: C19.1 R11.2 | length 1.5
  Top Layer w0.2: C19.1 33.15,81.2 R11.2@33.3,81.35
NetC19_2: C19.2 U.21 | length 2.2
  Top Layer w0.2: U.21 29.626,81.775 29.851,81.55 30.45,81.55 30.7,81.3 C19.2@30.7,81.2
NetC20_2: C20.2 U.19 | length 2.7
  Top Layer w0.2: U.19 28.4,80.5 C20.2
NetC21_2: C21.2 D1.2 Q1.1 R10.1 R17.2 | length 12.1
  Top Layer w0.2: D1.2 38.6,77.555 40.055,76.1 41.975,76.1 42.85,76.975 C21.2 42.55,77.3 Q1.1 43.45,80.4 43.925,80.875 R10.1 R17.2
NetC22_1: C22.1 U.4 | length 2.1
  Top Layer w0.2: C22.1 25.55,87.375 26,86.925 U.4
NetC22_2: C22.2 R20.1 | length 1.7
  Top Layer w0.2: R20.1 25.098,88.977 25.45,88.625 C22.2
NetC27_1: C27.1 L*1.1 L*.2 TP3.1
NetC28_1: C28.1 J*2.1 J*14.1 L*1.2
NetC29_1: C29.1 Q3.1 R21.1 | length 11.7
  Bottom Layer w1: Q3.1 59.4,8.958 v3(59.4,16.6)
  other v3: 59.4,14.2 59.4,15.4
NetD1_1: D1.1 Q1.2 R9.1 | length 3.6
  Top Layer w0.2: D1.1 40.525,80.275 Q1.2 40.65,81.827 R9.1
NetJ*4_1: J*4.1 Q3.2 R21.2 | length 7.4
  Top Layer w1: Q3.2 54,13.5
NetJ*5_1: J*5.1 Q3.3
NetL1_1: L1.1 R2.2 R3.2 U.12 U.13 U.14 U.14.1 | length 28.9
  Top Layer w0.2: R3.2 14.127,74 24,74 24,69 24.3,68.7 32.8,68.7 33.4,69.3 33.4,71.9 33.751,72.251 R2.2
NetP1_1: P1.1 R17.1 | length 3.2
  Top Layer w0.2: R17.1 46.445,78.475 P1.1
NetR1_1: R1.1 R4.2 U.3 | length 4.7
  Top Layer w0.2: U.3 26.65,86.35 27.4,87.1 R1.1 27.473,88.073 R4.2
NetR5_2: R5.2 U.18 | length 5.7
  Top Layer w0.2: U.18 27.525,80.475 27.525,79.901 29.226,78.2 31.023,78.2 31.65,78.827 R5.2
NetR6_2: R6.2 U.27 | length 10.2
  Top Layer w0.2: U.27 28.775,85.275 29.6,86.1 29.6,87.154 30.65,88.204 35.011,88.204 35.784,87.431 35.848,87.431 36.115,87.164 R6.2
NetR7_2: R7.2 U.25 | length 2.2
  Top Layer w0.2: U.25 28.8,83.8 29.55,83.8 30.45,84.7 R7.2
NetR8_2: R8.2 U.24 | length 1.8
  Top Layer w0.2: U.24 30.56,83.275 R8.2
NetR9_2: R9.2 R10.2 R18.1 | length 3.6
  Top Layer w0.2: R18.1 41.727,83.45 42.277,82.9 R9.2 43.775,81.9 R10.2
NetR19_1: R19.1 TP2.1 U.2 | length 12.3
  Top Layer w0.2: U.2 27.375,85.625 27.375,86.275 28.3,87.2 29.2,87.2 30.4,88.4 30.4,89.883 29.531,90.752 28.348,90.752 27.475,91.625 R19.1 27.5,91.725 TP2.1
NetR20_2: R20.2 U.5 U.6 | length 3.6
  Top Layer w0.2: R20.2 23.927,87.423 24.256,87.094 24.256,86.627 24.383,86.5 ; U.6 24.5,86.383 24.383,86.5 ; U.5 25,86.383 24.883,86.5 24.383,86.5
NetTP1_1: TP1.1 U.15 | length 13.1
  Top Layer w0.2: U.15 26,76.517 26.117,76.4 32.8,76.4 TP1.1
VCC: C1.1 C2.1 C3.1 C6.2 C7.2 C8.2 C18.2 J*9.1 R1.2 U.1 U.7 U.8 U.29 | length 9.9
  Top Layer w0.2: U.1 27.95,85.85 28.543,86.443 28.743,86.443 v3(28.8,86.5) ; R1.2 28.753,88.077 29.338,88.662 29.562,88.662 v3(29.6,88.7)
  Layer 2 w0.2: 25.7,87.9 26.5,88.7 v3(29.6,88.7) ; 25.8,86.4 25.9,86.5 v3(28.8,86.5)
  other v1: 7,87 8.5,87 10,87 11.5,87 13,87 14.5,87 16,87 17.5,87 19,87 20.5,87 22,87 7,88.5 8.5,88.5 10,88.5 11.5,88.5 13,88.5 14.5,88.5 16,88.5 17.5,88.5 19,88.5 20.5,88.5 22,88.5 7,90 8.5,90 10,90 11.5,90 13,90 14.5,90 16,90 17.5,90 19,90 20.5,90 22,90 7,91.5 8.5,91.5 10,91.5 11.5,91.5 13,91.5 14.5,91.5 16,91.5 17.5,91.5 19,91.5 20.5,91.5 22,91.5
  other v2: 24.4,84.1 26.2,84.2 25.25,84.225
VFB: C21.1 P1.3 Q1.3 R12.1 R13.1 R14.1 R15.1 R16.2 U.22 | length 31.2
  Top Layer w0.2: U.22 29.55,82.275 29.825,82 34,82 34.086,82.086 34.501,82.086 R12.1 R13.1 R13.1@36.164,82.285 ; 36.277,84.9 36.277,84.873 36.831,84.319 36.831,82.952 R13.1@36.164,82.285 ; v3(39.5,81.3) 39.5,81.317 39.2,81.617 R15.1 ; C21.1 41.55,78.35 Q1.3 41.6,80.8 41.453,80.947 41.453,82.547 41.3,82.7 40,82.7 39.852,82.552 39.468,82.552 R15.1 ; R13.1@36.164,82.285 R14.1 R15.1
  Layer 2 w0.2: v3(39.5,81.3) 41.2,83 P1.3
VINF: J*1.1 L*.1
VOUT: C9.1 C10.1 C11.1 C13.2 C14.2 C15.2 C24.2 C25.2 C26.2 C30.2 J*11.1 L1.2 P1.2 R12.2 R13.2 R14.2 R15.2 R18.2 | length 47.5
  Top Layer w0.2: L1.2@24,57.765 24,68.1 24.3,68.4 34.3,68.4 35.3,67.4 C13.2 ; R12.2 R13.2@36.036,83.515 ; v3(35.5,84.4) 35.547,84.353 35.547,84.069 35.769,83.846 35.769,83.783 R13.2@36.036,83.515 ; R13.2 R13.2@36.036,83.515 ; v3(37.8,84.4) R14.2 R15.2 40.458,83.515 R18.2 40.473,83.55 41.323,84.4 43.06,84.4 P1.2 52.883,80.46 53,80.577 53,80.7
  Bottom Layer w0.2: v3(35.5,84.4) v3(37.8,84.4)
  other v1: 17,61.5 19,61.5 21,61.5 23,61.5 25,61.5 27,61.5 29,61.5 31,61.5 33,61.5 35,61.5 37,61.5 41,61.5 43,61.5 45,61.5 47,61.5 49,61.5 53,61.5 55,61.5 57,61.5 59,61.5 61,61.5 63,61.5 16,63 18,63 20,63 22,63 24,63 26,63 28,63 30,63 32,63 34,63 36,63 38,63 40,63 42,63 44,63 46,63 48,63 50,63 52,63 54,63 56,63 58,63 60,63 62,63 17,64.5 19,64.5 21,64.5 23,64.5 25,64.5 27,64.5 29,64.5 31,64.5 33,64.5 35,64.5 37,64.5 39,64.5 41,64.5 43,64.5 45,64.5 47,64.5 49,64.5 51,64.5 53,64.5 55,64.5 57,64.5 59,64.5 61,64.5 63,64.5 57,66 59,66 61,66 63,66 57,67.5 59,67.5 61,67.5 63,67.5 57,69 59,69 61,69 63,69 57,70.5 59,70.5 61,70.5 63,70.5 57,72 59,72 61,72 63,72 57,73.5 59,73.5 61,73.5 63,73.5 57,75 59,75 61,75 63,75 57,76.5 59,76.5 61,76.5 63,76.5 57,78 59,78 61,78 63,78
pads on no net: ST1.1 ST2.1 ST3.1 ST4.1 ST5.1 ST6.1 ST7.1 ST8.1

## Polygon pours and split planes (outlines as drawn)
FGND on Top Layer "NONET_L01_P-001" (solid, pour order 45): 66.5,41.5 14.5,41.5 14.5,17.5 30.5,17.5 30.5,28.5 79,28.5 79,46.5 86,46.5 86,54.5 66.5,54.5 66.5,47
NetC28_1 on Top Layer "NONET_L01_P-001" (solid, pour order 43): 97,57 97,42.5 93.5,42.5 93.5,2.5 74.5,2.5 74.5,17.5 80,17.5 80,46 86.5,46 86.5,57
NetC29_1 on Top Layer "NONET_L01_P-001" (solid, pour order 38): 60,17.3 60,13.8 56.2,13.8 56.2,17.3
NetJ*4_1 on Top Layer "NONET_L01_P-001" (solid, pour order 37): 73.5,17.4 73.4,17.5 60.8,17.5 60.8,13.6 55.6,13.6 55.6,15.8 52.7,15.8 52.7,3 55.3,3 55.3,7.9 58,7.9 58,3 73.5,3
NetJ*5_1 on Top Layer "NONET_L01_P-001" (solid, pour order 36): 31.5,17.5 31.5,3 52.5,3 52.5,17.5
BGND on Top Layer "NONET_L01_P-001" (solid, pour order 35): 31.5,27.5 73.5,27.5 73.5,18 31.5,18
NetC27_1 on Top Layer "NONET_L01_P-001" (solid, pour order 34): 97,78 97,65.5 86,65.5 86,78
FGND on Top Layer "NONET_L01_P-001" (solid, pour order 33): 73,54 73,78 66.5,78 66.5,54
FGND on Top Layer "NONET_L01_P-001" (solid, pour order 29): 66.5,55 86.1,55 86.1,46.5 66.5,46.5
NetC28_1 on Top Layer "NONET_L01_P-001" (solid, pour order 28): 73.5,63 73.5,55.5 97,55.5 97,65 87,65 87,63
NetC27_1 on Top Layer "NONET_L01_P-001" (solid, pour order 27): 73.5,78 73.5,63.5 86.5,63.5 86.5,78
VINF on Top Layer "NONET_L01_P-001" (solid, pour order 26): 66.5,87.5 66.5,78.5 86.5,78.5 86.5,87.5
AGND on Top Layer "AGND_L01_P007" (solid, pour order 7): 31.2,87.6 31.2,82.3 34,82.3 34,84.1 35.5,84.1 35.5,87.6
AGND on Top Layer "AGND_L01_P011" (solid, pour order 11): 13,53 65,53 65,42.5 0.5,42.5 0.5,63.5 13,63.5
VOUT on Top Layer "VOUT_L01_P010" (solid, pour order 10): 14.5,66.5 14.5,53.5 65,53.5 65,87.5 52.5,87.5 52,87 52,74.5 47.25,69.75 43.133,66.5
AGND on Top Layer "AGND_L01_P005" (solid, pour order 5): 26.646,83.4 26.83,83.4 26.83,84.82 26.84,84.83 28.09,84.83 28.09,81.23 28.089,81.229 26.646,81.229
AGND on Top Layer "AGND_L01_P004" (solid, pour order 4): 24,83.4 26.83,83.4 26.83,84.82 26.84,84.83 28.09,84.83 28.09,81.23 28.089,81.229 23.921,81.229 23.921,83.321
NetL1_1 on Top Layer "NETL1_1_L01_P002" (solid, pour order 2): 24.2,81 23.6,81 22.3,79.7 20.4,79.7 17,76.3 17,70.8 31,70.8 31,76.1 25.6,76.1 25.6,79.7 25.6,81 24.121,81
AGND on Top Layer "AGND_L01_P001" (solid, pour order 1): 24,83.4 22.8,83.4 22.6,83.2 21.6,83.2 0.5,83.2 0.5,63 13,63 13,75 15.5,75 20.4,79.9 22.2,79.9 23.5,81.2 24,81.2
VCC on Top Layer "VCC_L01_P000" (solid, pour order 0): 24,83.6 0.5,83.6 0.5,94 6,94 6,99.5 22.5,99.5 22.5,86.2 22.6,86.1 23.1,85.6 23.6,85 24,85
BGND on Layer 2 "NONET_L01_P-001" (solid, pour order 40): 31.5,27.5 73.5,27.5 73.5,3 31.5,3
FGND on Layer 2 "NONET_L01_P-001" (solid, pour order 31): 66.5,87.5 66.5,46.5 97,46.5 97,87.5
VOUT on Layer 2 "VOUT_L03_P015" (solid, pour order 15): 14.5,66.6 14.5,53.5 65,53.5 65,87.5 52.5,87.5 52.1,87.1 52,87.1 52,74.6 43.9,66.5 14.6,66.5
AGND on Layer 2 "AGND_L03_P014" (solid, pour order 14): 28.1,81 28.1,67.5 13,67.5 13,53 65,53 65,42.5 0.5,42.5 0.5,83.2 26.7,83.2 26.7,81
VCC on Layer 2 "VCC_L03_P008" (solid, pour order 8): 0.5,83.5 26.5,83.5 26.5,85 26.5,99.5 6,99.5 6,94 0.5,94
AGND on Layer 1 "AGND_L02_P020" (solid, pour order 20): 26.8,99.3 27,99.5 49.9,99.5 49.9,76.2 33.2,76.2 32.9,76.5 32.9,80.3 27.1,80.3 26.8,80.6
AGND on Layer 1 "AGND_L02_P016" (solid, pour order 16): 0.5,94 0.5,42.5 65,42.5 65,87.5 50.5,87.5 50.4,87.4 50.4,75.9 32.9,75.9 32.7,76.1 32.7,80.1 26.9,80.1 26.7,80.3 26.7,99.5 6,99.5 6,94
BGND on Layer 1 "NONET_L01_P-001" (solid, pour order 39): 31.5,27.5 73.5,27.5 73.5,3 31.5,3
FGND on Layer 1 "NONET_L01_P-001" (solid, pour order 30): 66.5,87.5 66.5,46.5 97,46.5 97,87.5
AGND on Bottom Layer "AGND_L04_P024" (solid, pour order 24): 28.8,99.5 28.8,85.1 28.6,84.9 26.9,84.9 26.9,80.5 27.1,80.3 32.9,80.3 32.9,76.6 33.2,76.3 33.2,76.2 49.9,76.2 49.9,99.5
BGND on Bottom Layer "NONET_L01_P-001" (solid, pour order 42): 31.5,27.5 31.5,3 55.5,3 55.5,18 61,18 61,3 73.5,3 73.5,27.5
FGND on Bottom Layer "NONET_L01_P-001" (solid, pour order 32): 66.5,87.5 97,87.5 97,46.5 66.5,46.5
VOUT on Bottom Layer "VOUT_L04_P023" (solid, pour order 23): 14.5,66.5 14.5,53.5 64.9,53.5 65,53.6 65,87.5 52.5,87.5 50.4,87.5 50.4,73.8 43.1,66.5
AGND on Bottom Layer "AGND_L04_P022" (solid, pour order 22): 26.8,84.8 26.8,81.2 23.5,81.2 22.2,79.9 20.4,79.9 15.5,75 13,75 13,53 65,53 65,42.5 0.5,42.5 0.5,83.2 22.6,83.2 22.8,83.4 26.8,83.4
VCC on Bottom Layer "VCC_L04_P021" (solid, pour order 21): 6,94 0.5,94 0.5,83.6 26.6,83.6 26.6,85 28.2,85 28.6,85.4 28.6,99.5 6,99.5
no net on Bottom Solder "NONET_L04_P025" (solid, pour order 25): 23.9,85.4 28.6,85.4 28.6,80.7 23.9,80.7

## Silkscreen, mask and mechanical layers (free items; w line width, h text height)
Top Overlay:
  text "Master thesis" at 50.754,97.754 h1.52
  text "Switching power supply" at 50.754,95.662 h1.52
  text "Petr Sebesta" at 50.754,93.054 h1.52
Mechanical 1:
  the board outline again, w0.254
